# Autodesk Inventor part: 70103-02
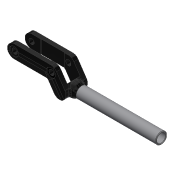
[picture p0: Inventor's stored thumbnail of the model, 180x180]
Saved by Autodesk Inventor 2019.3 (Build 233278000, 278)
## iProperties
Created: 2012-10
Part Number: 70103-02
Material: Ogólny
Document SubType Name: Modeling
Designer: CADENGINEERING4
Density: 1 g/cm^3
Appearance: Domyślna
Author: CADENGINEERING4
Revision Number: ÈÎºÎ
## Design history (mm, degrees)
feature "Ô²½Ç2"
feature "µ¹½Ç8"
node "Bryła1"
node "Bryła2"
